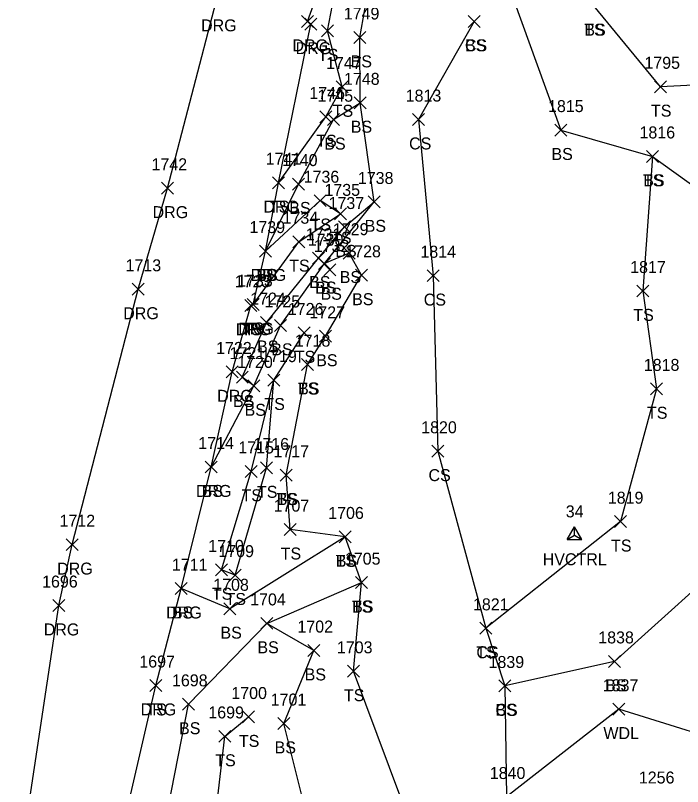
# Model space of a CAD drawing. Extents: x 1551995 to 1555700, y 777276 to 783130.
# Drawn here: x 1554731.6 to 1554843.1, y 778082.5 to 778211.4 of the extents above; entities that cross this region are included whole.
import ezdxf

# ---------------------------------------------------------------- set-up
doc = ezdxf.new("R2010")
doc.units = 0
for name, color, linetype in [('C_A', 7, 'Continuous'), ('C_I', 7, 'Continuous'), ('CPSM', 7, 'Continuous'), ('L_A', 7, 'Continuous'), ('L_I', 7, 'Continuous'), ('L_TIC', 7, 'Continuous'), ('LAWA', 7, 'Continuous'), ('LELB', 7, 'Continuous'), ('R_A', 7, 'Continuous'), ('R_I', 7, 'Continuous'), ('R_TIC', 7, 'Continuous'), ('RDG', 7, 'Continuous')]:
    doc.layers.add(name, color=color, linetype=linetype)

msp = doc.modelspace()

# ---------------------------------------------------------------- linework, layer by layer
at = {"layer": 'CPSM'}
for p, q in [((1554823.76, 778123.73), (1554825.01, 778125.89)), ((1554826.26, 778123.73), (1554825.01, 778125.89)), ((1554825.01, 778124.45), (1554825.01, 778125.89)), ((1554823.76, 778123.73), (1554825.01, 778124.45)), ((1554823.76, 778123.73), (1554826.26, 778123.73)), ((1554825.01, 778124.45), (1554825.01, 778124.45)), ((1554825.01, 778124.45), (1554826.26, 778123.73))]:
    msp.add_line(p, q, dxfattribs=at)
at = {"layer": 'L_TIC'}
for points in [[(1554807.26, 778209.35), (1554809.26, 778211.35)], [(1554809.26, 778209.35), (1554807.26, 778211.35)], [(1554807.26, 778209.35), (1554809.26, 778211.35)], [(1554809.26, 778209.35), (1554807.26, 778211.35)], [(1554782.74, 778207.76), (1554784.74, 778209.76)], [(1554784.74, 778207.76), (1554782.74, 778209.76)], [(1554788.17, 778206.67), (1554790.17, 778208.67)], [(1554790.17, 778206.67), (1554788.17, 778208.67)], [(1554785.21, 778198.41), (1554787.21, 778200.41)], [(1554787.21, 778198.41), (1554785.21, 778200.41)], [(1554838.38, 778198.43), (1554840.38, 778200.43)], [(1554840.38, 778198.43), (1554838.38, 778200.43)], [(1554788.2, 778195.75), (1554790.2, 778197.75)], [(1554790.2, 778195.75), (1554788.2, 778197.75)], [(1554788.2, 778195.75), (1554790.2, 778197.75)], [(1554790.2, 778195.75), (1554788.2, 778197.75)], [(1554782.46, 778193.4), (1554784.46, 778195.4)], [(1554784.46, 778193.4), (1554782.46, 778195.4)], [(1554783.77, 778192.93), (1554785.77, 778194.93)], [(1554785.77, 778192.93), (1554783.77, 778194.93)], [(1554797.94, 778192.95), (1554799.94, 778194.95)], [(1554799.94, 778192.95), (1554797.94, 778194.95)], [(1554821.72, 778191.19), (1554823.72, 778193.19)], [(1554823.72, 778191.19), (1554821.72, 778193.19)], [(1554837.05, 778186.79), (1554839.05, 778188.79)], [(1554839.05, 778186.79), (1554837.05, 778188.79)], [(1554837.05, 778186.79), (1554839.05, 778188.79)], [(1554839.05, 778186.79), (1554837.05, 778188.79)], [(1554774.55, 778182.39), (1554776.55, 778184.39)], [(1554776.55, 778182.39), (1554774.55, 778184.39)], [(1554777.92, 778182.17), (1554779.92, 778184.17)], [(1554779.92, 778182.17), (1554777.92, 778184.17)], [(1554781.51, 778179.39), (1554783.51, 778181.39)], [(1554783.51, 778179.39), (1554781.51, 778181.39)], [(1554790.52, 778179.18), (1554792.52, 778181.18)], [(1554792.52, 778179.18), (1554790.52, 778181.18)], [(1554790.52, 778179.18), (1554792.52, 778181.18)], [(1554792.52, 778179.18), (1554790.52, 778181.18)], [(1554784.94, 778177.19), (1554786.94, 778179.19)], [(1554786.94, 778177.19), (1554784.94, 778179.19)], [(1554785.61, 778174.99), (1554787.61, 778176.99)], [(1554787.61, 778174.99), (1554785.61, 778176.99)], [(1554777.95, 778172.53), (1554779.95, 778174.53)], [(1554779.95, 778172.53), (1554777.95, 778174.53)], [(1554772.41, 778170.97), (1554774.41, 778172.97)], [(1554774.41, 778170.97), (1554772.41, 778172.97)], [(1554772.41, 778170.97), (1554774.41, 778172.97)], [(1554774.41, 778170.97), (1554772.41, 778172.97)], [(1554786.35, 778170.62), (1554788.35, 778172.62)], [(1554788.35, 778170.62), (1554786.35, 778172.62)], [(1554781.24, 778169.78), (1554783.24, 778171.78)], [(1554783.24, 778169.78), (1554781.24, 778171.78)], [(1554782.24, 778168.86), (1554784.24, 778170.86)], [(1554784.24, 778168.86), (1554782.24, 778170.86)], [(1554782.24, 778168.86), (1554784.24, 778170.86)], [(1554784.24, 778168.86), (1554782.24, 778170.86)], [(1554783.15, 778167.83), (1554785.15, 778169.83)], [(1554785.15, 778167.83), (1554783.15, 778169.83)], [(1554788.42, 778166.92), (1554790.42, 778168.92)], [(1554790.42, 778166.92), (1554788.42, 778168.92)], [(1554800.39, 778166.85), (1554802.39, 778168.85)], [(1554802.39, 778166.85), (1554800.39, 778168.85)], [(1554835.43, 778164.29), (1554837.43, 778166.29)], [(1554837.43, 778164.29), (1554835.43, 778166.29)], [(1554769.94, 778161.89), (1554771.94, 778163.89)], [(1554771.94, 778161.89), (1554769.94, 778163.89)], [(1554770.35, 778162.02), (1554772.35, 778164.02)], [(1554772.35, 778162.02), (1554770.35, 778164.02)], [(1554772.54, 778159.02), (1554774.54, 778161.02)], [(1554774.54, 778159.02), (1554772.54, 778161.02)], [(1554774.92, 778158.54), (1554776.92, 778160.54)], [(1554776.92, 778158.54), (1554774.92, 778160.54)], [(1554778.87, 778157.29), (1554780.87, 778159.29)], [(1554780.87, 778157.29), (1554778.87, 778159.29)], [(1554782.42, 778156.72), (1554784.42, 778158.72)], [(1554784.42, 778156.72), (1554782.42, 778158.72)], [(1554779.4, 778151.99), (1554781.4, 778153.99)], [(1554781.4, 778151.99), (1554779.4, 778153.99)], [(1554779.4, 778151.99), (1554781.4, 778153.99)], [(1554781.4, 778151.99), (1554779.4, 778153.99)], [(1554768.52, 778149.9), (1554770.52, 778151.9)], [(1554770.52, 778149.9), (1554768.52, 778151.9)], [(1554773.8, 778149.4), (1554775.8, 778151.4)], [(1554775.8, 778149.4), (1554773.8, 778151.4)], [(1554773.8, 778149.4), (1554775.8, 778151.4)], [(1554775.8, 778149.4), (1554773.8, 778151.4)], [(1554770.44, 778148.43), (1554772.44, 778150.43)], [(1554772.44, 778148.43), (1554770.44, 778150.43)], [(1554770.44, 778148.43), (1554772.44, 778150.43)], [(1554772.44, 778148.43), (1554770.44, 778150.43)], [(1554837.72, 778147.94), (1554839.72, 778149.94)], [(1554839.72, 778147.94), (1554837.72, 778149.94)], [(1554801.18, 778137.51), (1554803.18, 778139.51)], [(1554803.18, 778137.51), (1554801.18, 778139.51)], [(1554763.29, 778134.87), (1554765.29, 778136.87)], [(1554765.29, 778134.87), (1554763.29, 778136.87)], [(1554772.56, 778134.72), (1554774.56, 778136.72)], [(1554774.56, 778134.72), (1554772.56, 778136.72)], [(1554769.98, 778134.14), (1554771.98, 778136.14)], [(1554771.98, 778134.14), (1554769.98, 778136.14)], [(1554775.84, 778133.51), (1554777.84, 778135.51)], [(1554777.84, 778133.51), (1554775.84, 778135.51)], [(1554775.84, 778133.51), (1554777.84, 778135.51)], [(1554777.84, 778133.51), (1554775.84, 778135.51)], [(1554831.72, 778125.74), (1554833.72, 778127.74)], [(1554833.72, 778125.74), (1554831.72, 778127.74)], [(1554776.52, 778124.41), (1554778.52, 778126.41)], [(1554778.52, 778124.41), (1554776.52, 778126.41)], [(1554785.7, 778123.19), (1554787.7, 778125.19)], [(1554787.7, 778123.19), (1554785.7, 778125.19)], [(1554785.7, 778123.19), (1554787.7, 778125.19)], [(1554787.7, 778123.19), (1554785.7, 778125.19)], [(1554765.03, 778117.69), (1554767.03, 778119.69)], [(1554767.03, 778117.69), (1554765.03, 778119.69)], [(1554767.3, 778116.81), (1554769.3, 778118.81)], [(1554769.3, 778116.81), (1554767.3, 778118.81)], [(1554767.3, 778116.81), (1554769.3, 778118.81)], [(1554769.3, 778116.81), (1554767.3, 778118.81)], [(1554788.42, 778115.55), (1554790.42, 778117.55)], [(1554790.42, 778115.55), (1554788.42, 778117.55)], [(1554788.42, 778115.55), (1554790.42, 778117.55)], [(1554790.42, 778115.55), (1554788.42, 778117.55)], [(1554758.31, 778114.55), (1554760.31, 778116.55)], [(1554760.31, 778114.55), (1554758.31, 778116.55)], [(1554766.43, 778111.18), (1554768.43, 778113.18)], [(1554768.43, 778111.18), (1554766.43, 778113.18)], [(1554772.6, 778108.74), (1554774.6, 778110.74)], [(1554774.6, 778108.74), (1554772.6, 778110.74)], [(1554772.6, 778108.74), (1554774.6, 778110.74)], [(1554774.6, 778108.74), (1554772.6, 778110.74)], [(1554809.18, 778107.91), (1554811.18, 778109.91)], [(1554811.18, 778107.91), (1554809.18, 778109.91)], [(1554809.18, 778107.91), (1554811.18, 778109.91)], [(1554811.18, 778107.91), (1554809.18, 778109.91)], [(1554780.49, 778104.2), (1554782.49, 778106.2)], [(1554782.49, 778104.2), (1554780.49, 778106.2)], [(1554830.67, 778102.38), (1554832.67, 778104.38)], [(1554832.67, 778102.38), (1554830.67, 778104.38)], [(1554787.09, 778100.73), (1554789.09, 778102.73)], [(1554789.09, 778100.73), (1554787.09, 778102.73)], [(1554754.05, 778098.35), (1554756.05, 778100.35)], [(1554756.05, 778098.35), (1554754.05, 778100.35)], [(1554812.35, 778098.28), (1554814.35, 778100.28)], [(1554814.35, 778098.28), (1554812.35, 778100.28)], [(1554812.35, 778098.28), (1554814.35, 778100.28)], [(1554814.35, 778098.28), (1554812.35, 778100.28)], [(1554759.51, 778095.21), (1554761.51, 778097.21)], [(1554761.51, 778095.21), (1554759.51, 778097.21)], [(1554831.42, 778094.39), (1554833.42, 778096.39)], [(1554833.42, 778094.39), (1554831.42, 778096.39)], [(1554769.54, 778093.09), (1554771.54, 778095.09)], [(1554771.54, 778093.09), (1554769.54, 778095.09)], [(1554769.54, 778093.09), (1554771.54, 778095.09)], [(1554771.54, 778093.09), (1554769.54, 778095.09)], [(1554775.47, 778092), (1554777.47, 778094)], [(1554777.47, 778092), (1554775.47, 778094)], [(1554765.59, 778089.85), (1554767.59, 778091.85)], [(1554767.59, 778089.85), (1554765.59, 778091.85)]]:
    msp.add_lwpolyline(points, dxfattribs=at)
at = {"layer": 'LAWA'}
msp.add_lwpolyline([(1554935.43, 778396.62), (1554932.57, 778365.34), (1554927.8, 778334.86), (1554903.79, 778283.5), (1554902.47, 778219.43), (1554891.48, 778177.56), (1554886.36, 778149.25), (1554864.38, 778127.13), (1554855.54, 778103.27), (1554855.62, 778088.16), (1554832.42, 778095.39), (1554813.64, 778080.72)], dxfattribs=at)
at = {"layer": 'LELB'}
for points in [[(1554773.41, 778171.97), (1554778.92, 778183.17), (1554784.77, 778193.93), (1554789.2, 778196.75), (1554789.17, 778207.67), (1554793.35, 778231.14), (1554800.41, 778253.93), (1554805.57, 778264.25), (1554823.29, 778287.72), (1554845.67, 778310.36), (1554878.45, 778338.48), (1554911.83, 778363.48), (1554935.43, 778396.62)], [(1554888.1, 778278.07), (1554881.6, 778269.1), (1554881.41, 778246.04), (1554876.74, 778227.33), (1554877.84, 778223.95), (1554878.69, 778212.64), (1554860.35, 778200.47), (1554839.38, 778199.43), (1554828.22, 778212.97), (1554822.86, 778217.91), (1554830.88, 778220.88), (1554825.41, 778230.38), (1554822.91, 778242.56), (1554824.36, 778250.86)], [(1554800.41, 778253.93), (1554822.72, 778192.19), (1554838.05, 778187.79), (1554853.05, 778176.97), (1554852.09, 778152.19), (1554855.34, 778134.52), (1554846.3, 778116.53), (1554831.67, 778103.38), (1554813.35, 778099.28)], [(1554775.55, 778183.39), (1554783.46, 778194.4), (1554786.21, 778199.41), (1554783.74, 778208.76), (1554788.23, 778232)], [(1554808.26, 778210.35), (1554798.94, 778193.95), (1554801.39, 778167.85), (1554802.18, 778138.51), (1554810.18, 778108.91), (1554813.35, 778099.28), (1554813.64, 778080.72)], [(1554776.84, 778134.51), (1554780.4, 778152.99), (1554783.42, 778157.72), (1554789.42, 778167.92), (1554787.35, 778171.62), (1554783.24, 778169.86), (1554791.52, 778180.18), (1554789.2, 778196.75)], [(1554838.05, 778187.79), (1554836.43, 778165.29), (1554838.72, 778148.94), (1554832.72, 778126.74), (1554810.18, 778108.91)], [(1554764.29, 778135.87), (1554771.44, 778149.43), (1554769.52, 778150.9), (1554773.54, 778160.02), (1554782.24, 778170.78), (1554786.61, 778175.99), (1554791.52, 778180.18)], [(1554771.35, 778163.02), (1554778.95, 778173.53), (1554785.94, 778178.19), (1554782.51, 778180.39), (1554773.41, 778171.97)], [(1554771.44, 778149.43), (1554775.92, 778159.54), (1554783.24, 778169.86), (1554784.15, 778168.83)], [(1554768.3, 778117.81), (1554773.56, 778135.72), (1554774.8, 778150.4), (1554779.87, 778158.29)], [(1554768.3, 778117.81), (1554766.03, 778118.69), (1554770.98, 778135.14), (1554774.8, 778150.4)], [(1554779.3, 777834.65), (1554783.83, 777890.02), (1554782.62, 777938.78), (1554771.14, 777988.74), (1554776.92, 778021.99), (1554786.75, 778049.64), (1554798.07, 778075.08), (1554788.09, 778101.73), (1554789.42, 778116.55), (1554786.7, 778124.19), (1554777.52, 778125.41), (1554776.84, 778134.51)], [(1554786.7, 778124.19), (1554767.43, 778112.18), (1554759.31, 778115.55)], [(1554753, 777988.87), (1554752.75, 778027.64), (1554754.81, 778066.96), (1554760.51, 778096.21), (1554773.6, 778109.74), (1554789.42, 778116.55)], [(1554776.92, 778021.99), (1554778.84, 778061.97), (1554781.91, 778071.15), (1554776.47, 778093), (1554781.49, 778105.2), (1554773.6, 778109.74)], [(1554759.44, 778026.67), (1554763.34, 778062.61), (1554766.59, 778090.85), (1554770.54, 778094.09)]]:
    msp.add_lwpolyline(points, dxfattribs=at)
at = {"layer": 'R_TIC'}
for points in [[(1554779.41, 778209.35), (1554781.41, 778211.35)], [(1554781.41, 778209.35), (1554779.41, 778211.35)], [(1554779.94, 778208.88), (1554781.94, 778210.88)], [(1554781.94, 778208.88), (1554779.94, 778210.88)], [(1554774.55, 778182.39), (1554776.55, 778184.39)], [(1554776.55, 778182.39), (1554774.55, 778184.39)], [(1554756.04, 778181.47), (1554758.04, 778183.47)], [(1554758.04, 778181.47), (1554756.04, 778183.47)], [(1554772.41, 778170.97), (1554774.41, 778172.97)], [(1554774.41, 778170.97), (1554772.41, 778172.97)], [(1554751.14, 778164.58), (1554753.14, 778166.58)], [(1554753.14, 778164.58), (1554751.14, 778166.58)], [(1554769.94, 778161.89), (1554771.94, 778163.89)], [(1554771.94, 778161.89), (1554769.94, 778163.89)], [(1554770.35, 778162.02), (1554772.35, 778164.02)], [(1554772.35, 778162.02), (1554770.35, 778164.02)], [(1554766.84, 778150.77), (1554768.84, 778152.77)], [(1554768.84, 778150.77), (1554766.84, 778152.77)], [(1554763.29, 778134.87), (1554765.29, 778136.87)], [(1554765.29, 778134.87), (1554763.29, 778136.87)], [(1554740.1, 778121.89), (1554742.1, 778123.89)], [(1554742.1, 778121.89), (1554740.1, 778123.89)], [(1554758.31, 778114.55), (1554760.31, 778116.55)], [(1554760.31, 778114.55), (1554758.31, 778116.55)], [(1554737.87, 778111.72), (1554739.87, 778113.72)], [(1554739.87, 778111.72), (1554737.87, 778113.72)], [(1554754.05, 778098.35), (1554756.05, 778100.35)], [(1554756.05, 778098.35), (1554754.05, 778100.35)]]:
    msp.add_lwpolyline(points, dxfattribs=at)
at = {"layer": 'RDG'}
for points in [[(1554731.76, 777736.57), (1554744.54, 777760.39), (1554749.58, 777791.25), (1554744.63, 777884.27), (1554742.18, 777937.77), (1554733.78, 777989.36), (1554731.62, 778029.74), (1554732.87, 778072.64), (1554738.87, 778112.72), (1554741.1, 778122.89), (1554752.14, 778165.58), (1554757.04, 778182.47), (1554765.14, 778213.69), (1554774.89, 778246.18), (1554785.77, 778269.3), (1554800.7, 778290.2), (1554833.81, 778326.22), (1554863.94, 778353.44), (1554894.55, 778381.82), (1554916.32, 778408.8)], [(1554765.41, 777786.83), (1554760.87, 777887.93), (1554755.21, 777940.6), (1554748.12, 777988.97), (1554746.63, 778028.6), (1554748.07, 778068.94), (1554755.05, 778099.35), (1554759.31, 778115.55), (1554764.29, 778135.87), (1554767.84, 778151.77), (1554770.94, 778162.89), (1554771.35, 778163.02), (1554773.41, 778171.97), (1554775.55, 778183.39), (1554780.94, 778209.88), (1554780.41, 778210.35), (1554788.23, 778232), (1554795.94, 778253.78), (1554801.81, 778267.78), (1554821.53, 778293.59), (1554841.19, 778314.82), (1554873.15, 778342.35), (1554907.49, 778367.57), (1554931.47, 778399.39)]]:
    msp.add_lwpolyline(points, dxfattribs=at)

# ---------------------------------------------------------------- texts
at = {"layer": 'C_A'}
msp.add_text('HVCTRL', height=2, dxfattribs=at).set_placement((1554819.7, 778119.45))
at = {"layer": 'C_I'}
msp.add_text('34', height=2, dxfattribs=at).set_placement((1554823.55, 778127.45))
at = {"layer": 'L_A'}
for s, p in [('TS', (1554826.63, 778207.97)), ('BS', (1554826.66, 778207.97)), ('CS', (1554806.71, 778205.35)), ('BS', (1554806.71, 778205.35)), ('TS', (1554782.15, 778203.76)), ('BS', (1554787.61, 778202.67)), ('TS', (1554784.62, 778194.41)), ('TS', (1554837.79, 778194.43)), ('BS', (1554787.64, 778191.75)), ('BS', (1554787.64, 778191.75)), ('TS', (1554781.87, 778189.4)), ('BS', (1554783.21, 778188.93)), ('CS', (1554797.38, 778188.95)), ('BS', (1554821.16, 778187.19)), ('TS', (1554836.46, 778182.79)), ('BS', (1554836.49, 778182.79)), ('TS', (1554773.96, 778178.39)), ('BS', (1554777.36, 778178.17)), ('TS', (1554780.92, 778175.39)), ('BS', (1554789.96, 778175.18)), ('BS', (1554789.96, 778175.18)), ('TS', (1554784.35, 778173.19)), ('BS', (1554785.05, 778170.99)), ('TS', (1554777.35, 778168.53)), ('TS', (1554771.82, 778166.97)), ('BS', (1554771.85, 778166.97)), ('BS', (1554785.79, 778166.62)), ('BS', (1554780.68, 778165.78)), ('BS', (1554781.68, 778164.86)), ('BS', (1554781.68, 778164.86)), ('BS', (1554782.59, 778163.83)), ('BS', (1554787.86, 778162.92)), ('CS', (1554799.83, 778162.85)), ('TS', (1554834.84, 778160.29)), ('TS', (1554769.35, 778157.89)), ('TS', (1554769.76, 778158.02)), ('BS', (1554771.98, 778155.02)), ('BS', (1554774.36, 778154.54)), ('TS', (1554778.28, 778153.29)), ('BS', (1554781.86, 778152.72)), ('TS', (1554778.81, 778147.99)), ('BS', (1554778.84, 778147.99)), ('BS', (1554767.96, 778145.9)), ('TS', (1554773.21, 778145.4)), ('TS', (1554773.21, 778145.4)), ('BS', (1554769.89, 778144.43)), ('BS', (1554769.89, 778144.43)), ('TS', (1554837.13, 778143.94)), ('CS', (1554800.62, 778133.51)), ('BS', (1554762.73, 778130.87)), ('TS', (1554771.97, 778130.72)), ('TS', (1554769.38, 778130.14)), ('TS', (1554775.25, 778129.51)), ('BS', (1554775.28, 778129.51)), ('TS', (1554831.12, 778121.74)), ('TS', (1554775.93, 778120.41)), ('TS', (1554785.11, 778119.19)), ('BS', (1554785.14, 778119.19)), ('TS', (1554764.44, 778113.69)), ('TS', (1554766.71, 778112.81)), ('TS', (1554766.71, 778112.81)), ('TS', (1554787.83, 778111.55)), ('BS', (1554787.86, 778111.55)), ('BS', (1554757.75, 778110.55)), ('BS', (1554765.87, 778107.18)), ('BS', (1554772.04, 778104.74)), ('BS', (1554772.04, 778104.74)), ('TS', (1554808.59, 778103.91)), ('CS', (1554808.62, 778103.91)), ('BS', (1554779.93, 778100.2)), ('BS', (1554830.11, 778098.38)), ('TS', (1554786.5, 778096.73)), ('TS', (1554753.46, 778094.35)), ('CS', (1554811.8, 778094.28)), ('BS', (1554811.8, 778094.28)), ('BS', (1554758.95, 778091.21)), ('WDL', (1554829.84, 778090.39)), ('TS', (1554768.95, 778089.09)), ('TS', (1554768.95, 778089.09)), ('BS', (1554774.91, 778088)), ('TS', (1554765, 778085.85))]:
    msp.add_text(s, height=2, dxfattribs=at).set_placement(p)
at = {"layer": 'L_I'}
for s, p in [('1749', (1554786.47, 778210.67)), ('1747', (1554783.51, 778202.41)), ('1795', (1554836.69, 778202.43)), ('1748', (1554786.51, 778199.75)), ('1748', (1554786.51, 778199.75)), ('1746', (1554780.72, 778197.4)), ('1745', (1554782.08, 778196.93)), ('1813', (1554796.81, 778196.95)), ('1815', (1554820.59, 778195.19)), ('1816', (1554835.87, 778190.79)), ('1816', (1554835.87, 778190.79)), ('1741', (1554773.42, 778186.39)), ('1740', (1554776.14, 778186.17)), ('1736', (1554779.76, 778183.39)), ('1738', (1554788.82, 778183.18)), ('1738', (1554788.82, 778183.18)), ('1735', (1554783.24, 778181.19)), ('1737', (1554783.92, 778178.99)), ('1734', (1554776.25, 778176.53)), ('1739', (1554770.71, 778174.97)), ('1739', (1554770.71, 778174.97)), ('1729', (1554784.65, 778174.62)), ('1731', (1554780.12, 778173.78)), ('1730', (1554780.46, 778172.86)), ('1730', (1554780.46, 778172.86)), ('1732', (1554781.45, 778171.83)), ('1728', (1554786.72, 778170.92)), ('1814', (1554799.27, 778170.85)), ('1817', (1554834.31, 778168.29)), ('1723', (1554768.24, 778165.89)), ('1733', (1554768.65, 778166.02)), ('1724', (1554770.84, 778163.02)), ('1725', (1554773.23, 778162.54)), ('1726', (1554777.12, 778161.29)), ('1727', (1554780.72, 778160.72)), ('1718', (1554778.28, 778155.99)), ('1718', (1554778.28, 778155.99)), ('1721', (1554767.39, 778153.9)), ('1720', (1554768.66, 778152.43)), ('1720', (1554768.66, 778152.43)), ('1719', (1554772.67, 778153.4)), ('1719', (1554772.67, 778153.4)), ('1818', (1554836.59, 778151.94)), ('1820', (1554799.4, 778141.51)), ('1714', (1554762.16, 778138.87)), ('1716', (1554771.38, 778138.72)), ('1715', (1554768.85, 778138.14)), ('1717', (1554774.72, 778137.51)), ('1717', (1554774.72, 778137.51)), ('1819', (1554830.58, 778129.74)), ('1707', (1554774.75, 778128.41)), ('1706', (1554783.87, 778127.19)), ('1706', (1554783.87, 778127.19)), ('1710', (1554763.82, 778121.69)), ('1709', (1554765.52, 778120.81)), ('1709', (1554765.52, 778120.81)), ('1705', (1554786.65, 778119.55)), ('1705', (1554786.65, 778119.55)), ('1711', (1554757.75, 778118.55)), ('1708', (1554764.66, 778115.18)), ('1704', (1554770.83, 778112.74)), ('1704', (1554770.83, 778112.74)), ('1821', (1554808.05, 778111.91)), ('1821', (1554808.05, 778111.91)), ('1702', (1554778.72, 778108.2)), ('1838', (1554828.98, 778106.38)), ('1703', (1554785.32, 778104.73)), ('1697', (1554752.31, 778102.35)), ('1839', (1554810.65, 778102.28)), ('1839', (1554810.65, 778102.28)), ('1698', (1554757.77, 778099.21)), ('1837', (1554829.73, 778098.39)), ('1700', (1554767.68, 778097.09)), ('1700', (1554767.68, 778097.09)), ('1701', (1554774.26, 778096)), ('1699', (1554763.84, 778093.85)), ('1840', (1554810.86, 778083.72)), ('1840', (1554810.86, 778083.72)), ('1840', (1554810.86, 778083.72)), ('1256', (1554835.76, 778082.97)), ('1256', (1554835.76, 778082.97))]:
    msp.add_text(s, height=2, dxfattribs=at).set_placement(p)
at = {"layer": 'R_A'}
for p in [(1554762.63, 778208.69), (1554777.9, 778205.35), (1554778.43, 778204.88), (1554773.04, 778178.39), (1554754.53, 778177.47), (1554770.9, 778166.97), (1554749.62, 778160.58), (1554768.42, 778157.89), (1554768.83, 778158.02), (1554765.32, 778146.77), (1554761.78, 778130.87), (1554738.59, 778117.89), (1554756.8, 778110.55), (1554736.35, 778107.72), (1554752.54, 778094.35)]:
    msp.add_text('DRG', height=2, dxfattribs=at).set_placement(p)
at = {"layer": 'R_I'}
for s, p in [('1741', (1554773.42, 778186.39)), ('1742', (1554754.35, 778185.47)), ('1739', (1554770.71, 778174.97)), ('1713', (1554750.01, 778168.58)), ('1723', (1554768.24, 778165.89)), ('1733', (1554768.65, 778166.02)), ('1722', (1554765.14, 778154.77)), ('1714', (1554762.16, 778138.87)), ('1712', (1554738.98, 778125.89)), ('1711', (1554757.75, 778118.55)), ('1696', (1554736.07, 778115.72)), ('1697', (1554752.31, 778102.35))]:
    msp.add_text(s, height=2, dxfattribs=at).set_placement(p)

doc.saveas('drawing.dxf')
